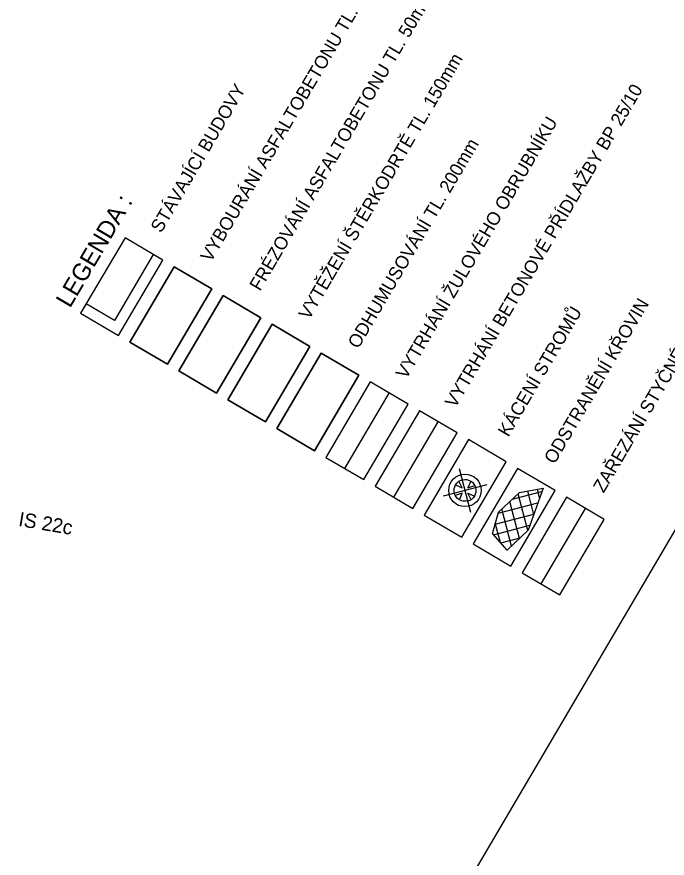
# Model space of a CAD drawing. Extents: x -559605 to -559051, y -1075984 to -1075185.
# Drawn here: x -559184.3 to -559124.9, y -1075414.9 to -1075338 of the extents above; entities that cross this region are included whole.
import ezdxf

# ---------------------------------------------------------------- set-up
doc = ezdxf.new("R2010")
doc.units = 0
for name, color, linetype in [('Legenda', 7, 'Continuous'), ('Ramecek_rozpiska', 7, 'Continuous'), ('Svisle DZ stavajici', 7, 'Continuous')]:
    doc.layers.add(name, color=color, linetype=linetype)

msp = doc.modelspace()

# ---------------------------------------------------------------- linework, layer by layer
at = {"layer": 'Legenda'}
for p, q in [((-559154.312, -1075379.253), (-559150.259, -1075372.356)), ((-559149.828, -1075381.888), (-559145.776, -1075374.991)), ((-559143.853, -1075379.252), (-559142.814, -1075383.254)), ((-559141.333, -1075380.734), (-559145.335, -1075381.773)), ((-559144.271, -1075380.929), (-559144.191, -1075380.739)), ((-559144.191, -1075380.739), (-559144.072, -1075380.579)), ((-559144.191, -1075380.739), (-559143.58, -1075381.008)), ((-559144.072, -1075380.579), (-559143.882, -1075380.408)), ((-559143.882, -1075380.408), (-559143.612, -1075380.298)), ((-559143.58, -1075381.008), (-559143.882, -1075380.408)), ((-559143.612, -1075380.298), (-559143.332, -1075380.257)), ((-559143.332, -1075380.257), (-559143.152, -1075380.267)), ((-559143.152, -1075380.267), (-559143.002, -1075380.317)), ((-559142.812, -1075380.396), (-559143.08, -1075381.006)), ((-559143.08, -1075381.006), (-559142.431, -1075380.805)), ((-559143.002, -1075380.317), (-559142.812, -1075380.396)), ((-559142.812, -1075380.396), (-559142.651, -1075380.516)), ((-559142.651, -1075380.516), (-559142.521, -1075380.676)), ((-559142.521, -1075380.676), (-559142.431, -1075380.805)), ((-559142.431, -1075380.805), (-559142.37, -1075380.975)), ((-559144.32, -1075381.08), (-559144.271, -1075380.929)), ((-559144.319, -1075381.33), (-559144.32, -1075381.08)), ((-559144.289, -1075381.54), (-559144.319, -1075381.33)), ((-559144.229, -1075381.709), (-559144.289, -1075381.54)), ((-559143.579, -1075381.508), (-559144.229, -1075381.709)), ((-559143.847, -1075382.119), (-559143.579, -1075381.508)), ((-559142.778, -1075382.106), (-559143.079, -1075381.506)), ((-559143.079, -1075381.506), (-559142.468, -1075381.775)), ((-559142.389, -1075381.585), (-559142.468, -1075381.775)), ((-559142.339, -1075381.435), (-559142.389, -1075381.585)), ((-559142.37, -1075380.975), (-559142.339, -1075381.185)), ((-559142.339, -1075381.185), (-559142.339, -1075381.435)), ((-559139.007, -1075382.067), (-559136.306, -1075381.366)), ((-559137.595, -1075384.928), (-559138.466, -1075381.573)), ((-559137.048, -1075383.455), (-559137.603, -1075381.316)), ((-559136.511, -1075381.942), (-559136.718, -1075381.145)), ((-559144.138, -1075381.839), (-559144.229, -1075381.709)), ((-559144.007, -1075381.999), (-559144.138, -1075381.839)), ((-559143.847, -1075382.119), (-559144.007, -1075381.999)), ((-559143.658, -1075382.198), (-559143.847, -1075382.119)), ((-559143.507, -1075382.248), (-559143.658, -1075382.198)), ((-559143.257, -1075382.247), (-559143.507, -1075382.248)), ((-559142.978, -1075382.206), (-559143.257, -1075382.247)), ((-559142.778, -1075382.106), (-559142.978, -1075382.206)), ((-559142.588, -1075381.935), (-559142.778, -1075382.106)), ((-559142.468, -1075381.775), (-559142.588, -1075381.935)), ((-559138.34, -1075385.641), (-559139.218, -1075382.26)), ((-559140.311, -1075383.336), (-559136.67, -1075382.39)), ((-559139.084, -1075386.354), (-559139.969, -1075382.947)), ((-559136.38, -1075389.793), (-559132.327, -1075382.895)), ((-559140.587, -1075384.337), (-559137.033, -1075383.415)), ((-559140.728, -1075385.304), (-559137.397, -1075384.439)), ((-559140.1, -1075386.023), (-559140.562, -1075384.245)), ((-559140.066, -1075386.062), (-559138.3, -1075385.603))]:
    msp.add_line(p, q, dxfattribs=at)
for points in [[(-559175.002, -1075367.092), (-559170.949, -1075360.195), (-559174.397, -1075358.168), (-559178.451, -1075365.065)], [(-559178.451, -1075365.065), (-559175.002, -1075367.092), (-559170.949, -1075360.195), (-559171.811, -1075359.689), (-559175.358, -1075365.723), (-559177.944, -1075364.203)], [(-559173.968, -1075367.7), (-559169.914, -1075360.803), (-559166.466, -1075362.83), (-559170.519, -1075369.727)], [(-559170.519, -1075369.727), (-559166.466, -1075362.83), (-559169.914, -1075360.803), (-559173.968, -1075367.7)], [(-559169.485, -1075370.335), (-559165.431, -1075363.438), (-559161.983, -1075365.465), (-559166.036, -1075372.362)], [(-559166.036, -1075372.362), (-559161.983, -1075365.465), (-559165.431, -1075363.438), (-559169.485, -1075370.335)], [(-559165.002, -1075372.97), (-559160.948, -1075366.073), (-559157.5, -1075368.1), (-559161.554, -1075374.997)], [(-559161.554, -1075374.997), (-559157.5, -1075368.1), (-559160.948, -1075366.073), (-559165.002, -1075372.97)], [(-559160.519, -1075375.605), (-559156.465, -1075368.708), (-559153.017, -1075370.735), (-559157.071, -1075377.632)], [(-559157.071, -1075377.632), (-559153.017, -1075370.735), (-559156.465, -1075368.708), (-559160.519, -1075375.605)], [(-559152.588, -1075380.267), (-559148.534, -1075373.37), (-559151.982, -1075371.343), (-559156.036, -1075378.24)], [(-559148.104, -1075382.901), (-559144.051, -1075376.005), (-559147.499, -1075373.978), (-559151.553, -1075380.875)], [(-559143.622, -1075385.536), (-559139.568, -1075378.639), (-559143.016, -1075376.613), (-559147.07, -1075383.509)], [(-559139.139, -1075388.171), (-559135.085, -1075381.274), (-559138.534, -1075379.247), (-559142.587, -1075386.144)], [(-559140.828, -1075385.212), (-559140.283, -1075383.234), (-559138.343, -1075381.46), (-559136.192, -1075381.042), (-559137.557, -1075384.892), (-559139.48, -1075386.733), (-559140.787, -1075385.236)], [(-559134.655, -1075390.806), (-559130.602, -1075383.909), (-559134.05, -1075381.882), (-559138.104, -1075388.779)]]:
    msp.add_lwpolyline(points, close=True, dxfattribs=at)
msp.add_circle((-559143.334, -1075381.253), 1.487, dxfattribs=at)
at = {"layer": 'Ramecek_rozpiska'}
msp.add_line((-559476.525, -1075984.455), (-559050.892, -1075260.275), dxfattribs=at)

# ---------------------------------------------------------------- texts
at = {"layer": 'Legenda'}
for s, height, p in [('VYBOURÁNÍ ASFALTOBETONU TL. 150mm', 1.2, (-559166.547, -1075360.463)), ('FRÉZOVÁNÍ ASFALTOBETONU TL. 50mm ', 1.2, (-559162.064, -1075363.097)), ('VYTĚŽENÍ ŠTĚRKODRTĚ TL. 150mm', 1.2, (-559157.581, -1075365.732)), ('STÁVAJÍCÍ BUDOVY', 1.2, (-559171.097, -1075357.788)), ('VYTRHÁNÍ BETONOVÉ PŘÍDLAŽBY BP 25/10', 1.2, (-559144.212, -1075373.79)), ('VYTRHÁNÍ ŽULOVÉHO OBRUBNÍKU', 1.2, (-559148.695, -1075371.155)), ('ODHUMUSOVÁNÍ TL. 200mm ', 1.2, (-559153.08, -1075368.378)), ('LEGENDA : ', 1.6, (-559179.424, -1075364.657)), ('ZAŘEZÁNÍ STYČNÉ SPÁRY ASFALTU', 1.2, (-559130.664, -1075381.552)), ('ODSTRANĚNÍ KŘOVIN', 1.2, (-559135.148, -1075378.918)), ('KÁCENÍ STROMŮ', 1.2, (-559139.369, -1075376.437))]:
    msp.add_text(s, height=height, rotation=59.55531, dxfattribs=at).set_placement(p)
at = {"layer": 'Svisle DZ stavajici'}
msp.add_text('IS 22c', height=1.3065, rotation=350.37405, dxfattribs=at).set_placement((-559184.193, -1075384.498))

doc.saveas('drawing.dxf')
